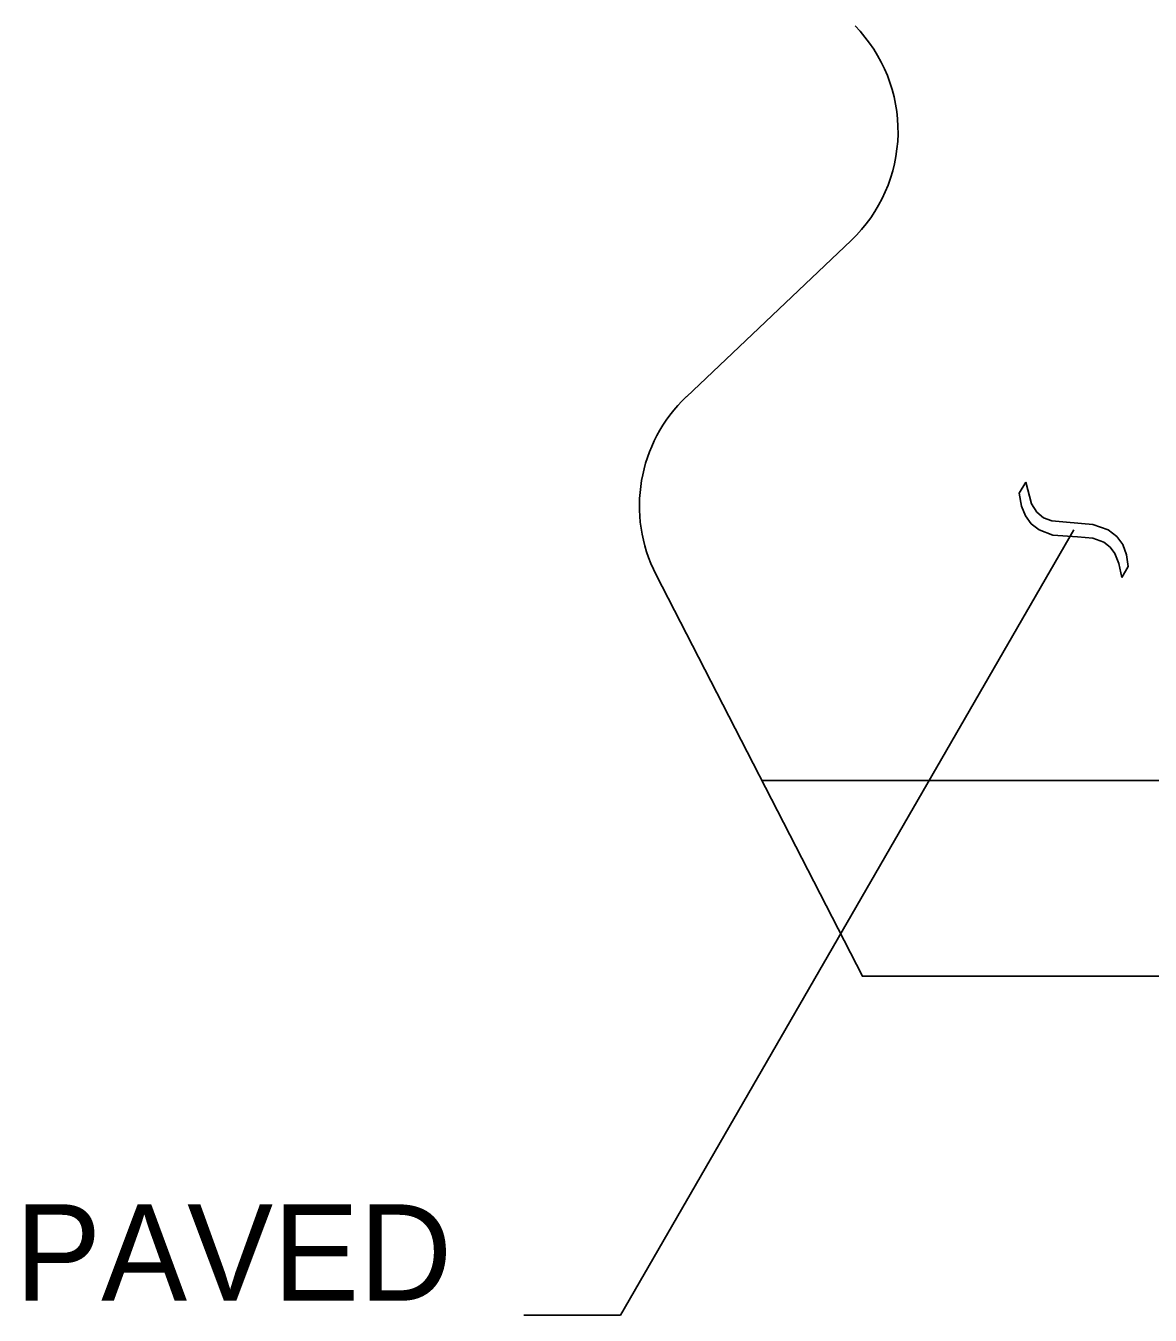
# Model space of a CAD drawing. Extents: x 99862 to 104211, y 98939 to 105076.
# Drawn here: x 101872.2 to 102058.9, y 100276.6 to 100490.7 of the extents above; entities that cross this region are included whole.
import ezdxf

# ---------------------------------------------------------------- set-up
doc = ezdxf.new("R2010")
doc.units = 0
for name, color, linetype in [('Level 15', 7, 'Continuous'), ('Level 20', 7, 'Continuous'), ('Level 50', 7, 'Continuous'), ('Level 8', 7, 'Continuous')]:
    doc.layers.add(name, color=color, linetype=linetype)

msp = doc.modelspace()

# ---------------------------------------------------------------- linework, layer by layer
at = {"layer": 'Level 15'}
for p, q in [((102038.24, 100414.91), (102037.18, 100413.08)), ((102039.22, 100411.35), (102038.24, 100414.91)), ((102037.18, 100413.08), (102037.54, 100410.96)), ((102037.54, 100410.96), (102038.19, 100409.31)), ((102040.09, 100409.95), (102039.22, 100411.35)), ((102038.19, 100409.31), (102039.14, 100408)), ((102041.18, 100409.03), (102040.09, 100409.95)), ((102042.58, 100408.5), (102041.18, 100409.03)), ((102045, 100408.3), (102042.58, 100408.5)), ((102046.24, 100407), (101970.95, 100276.61)), ((102039.14, 100408), (102040.47, 100407)), ((102040.47, 100407), (102042.77, 100406.11)), ((102049.39, 100407.92), (102045, 100408.3)), ((102051.95, 100407), (102049.39, 100407.92)), ((102053.35, 100405.92), (102051.95, 100407)), ((102042.77, 100406.11), (102046.85, 100405.84)), ((102046.85, 100405.84), (102049.39, 100405.62)), ((102049.39, 100405.62), (102051.2, 100404.98)), ((102051.2, 100404.98), (102052.25, 100404.16)), ((102054.37, 100404.55), (102053.35, 100405.92)), ((102055, 100402.88), (102054.37, 100404.55)), ((102052.25, 100404.16), (102053.06, 100403.07)), ((102053.06, 100403.07), (102053.68, 100401.44)), ((102055.25, 100400.91), (102055, 100402.88)), ((102053.68, 100401.44), (102054.2, 100399.08)), ((102054.2, 100399.08), (102055.25, 100400.91)), ((101954.95, 100276.61), (101970.95, 100276.61))]:
    msp.add_line(p, q, dxfattribs=at)
at = {"layer": 'Level 50'}
for points in [[(101981.91, 100429.12), (102009.26, 100455.07)], [(102367.15, 100332.9), (102011.14, 100332.9), (101976.88, 100399.56)]]:
    msp.add_lwpolyline(points, dxfattribs=at)
for centre, start, end in [((101992.05, 100473.2), 313.4926, 44.4213), ((101999.12, 100410.99), 133.4926, 207.1985)]:
    msp.add_arc(centre, 25, start, end, dxfattribs=at)
at = {"layer": 'Level 8'}
for p, q in [((101994.44, 100365.4), (102391.67, 100365.4)), ((102011.14, 100332.9), (102367.15, 100332.9))]:
    msp.add_line(p, q, dxfattribs=at)

# ---------------------------------------------------------------- texts
at = {"layer": 'Level 20'}
msp.add_text('PAVED', height=16, dxfattribs=at).set_placement((101870.49, 100279.02))

doc.saveas('drawing.dxf')
